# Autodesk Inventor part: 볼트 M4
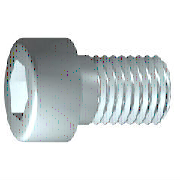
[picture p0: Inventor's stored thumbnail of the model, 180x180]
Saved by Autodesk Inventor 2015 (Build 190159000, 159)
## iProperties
IsCustomPart: 1
Created: 2012-02
Part Number: 볼트 M4
Material: 스테인리스강
Description: 6각 소켓 머리 캡 나사
Document SubType Name: Modeling
Standard: ISO 4762
Designer: mduedu
Standard Revision: Fourth edition 2004-03-01
Standards Organization: ISO
Language: ko-KR
Size Designation: M4 x 10
Categories: <MemberInstance><Categories><Category DisplayName="조임쇠" InternalName="e4da775c-781d-43d5-af7c-5136215cf5a6" Mnemonic="FSTN"><Category DisplayName="볼트" InternalN
Density: 7.75 g/cm^3
Appearance: 반광택
Author: mduedu
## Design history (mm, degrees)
sketch "스케치1"
  geometry: L1 (-1, 0)-(10, 0); L2 (10, 0)-(10, 2); L3 (10, 2)-(1.75, 2); L4 (1.75, 2)-(1.32, 2); L5 (1.32, 2)-(0, 2); L6 (0, 2)-(0, 3.5); L7 (0, 3.5)-(-4, 3.5); L8 (-4, 3.5)-(-4, 1.732); L9 (-4, 1.732)-(-2, 1.732); L10 (-2, 1.732)-(-1, 0); L11 (-6.8, 0)-(12.8, 0) reference; L12 (0, -0.7)-(0, 4.2) reference; L13 (1.75, 2)-(0, 2)
  constraints: 22 end point, 6 parallel, 2 collinear, 2 perpendicular, 1 horizontal, 1 point on line
  dimensions: "d1" = 8.25 distance from line of L3.end L2 (= GEL); "d2" = 0.42952 distance of L4.end L3.end (computed from GAL); "d3" = 4 distance between parallel lines of L8 L6 (= KOH); "d4" = 2 distance of L8.end L9.end (= INTI); "d5" = 60 deg angle of L10 L1; "d6" = 4 diameter of L3 L1 (= GD); "d7" = 4 diameter of L5 L1 (= BDM); "d8" = 3.4641 diameter of L9 L1 (= 1.1547 x SW); "d9" = 7 diameter of L7 L1 (= KOD); "d26" = 10 distance between parallel lines of L12 L2 (= NLG)
revolve "본체" sketch "스케치1" stored, may be unused: angle "d10" = 90 deg
sketch "스케치2"
  geometry: L1 (0, -4.9)-(0, 4.9) reference; L2 (-4.9, 0)-(4.9, 0) reference; L3 (1.732, 0)-(0.866, -1.5); L4 (0.866, -1.5)-(-0.866, -1.5); L5 (-0.866, -1.5)-(-1.732, 0); L6 (-1.732, 0)-(-0.866, 1.5); L7 (-0.866, 1.5)-(0.866, 1.5); L8 (0.866, 1.5)-(1.732, 0); 2 further points
  constraints: 12 end point, 1 coincident, 1 horizontal alignment, 1 point on line, 12 other
extrude "슬롯" join sketch "스케치2" stored distance "d11" = 10; taper "d12" = 0 deg
workplane "Work Plane1"
body "Solid1"
fillet "모깎기1" dims "d17" = 0.4 (= RR)
feature "스레드" dims "d13" = 8.25 (= GEL), "d14" = 0
chamfer "모따기1" distance "d15" = 0.42941 (= -0.5 x SPD + 0.5 x GD); stored, may be unused: second distance "d16" = 0.42941 (= GUL), angle "d27" = 45 deg
other parameters: "GD" = 4 [user parameter; used in 2 equation terms], "NLG" = 10 [user parameter; used in 1 equation term], "GEL" = 8.25 [user parameter; used in 2 equation terms], "KOD" = 7 [user parameter; used in 1 equation term], "KOH" = 4 [user parameter; used in 1 equation term], "INTI" = 2 [user parameter; used in 1 equation term], "GAL" = 0.42941 (= 0.61345 x PTC) [user parameter; used in 1 equation term], "GUL" = 0.42941 (= 0.61345 x PTC) [user parameter; used in 1 equation term], "BDM" = 4 (= NND) [user parameter; used in 1 equation term], "SW" = 3 [user parameter; used in 2 equation terms], "RR" = 0.4 [user parameter; used in 1 equation term], "SPD" = 3.14117 (= NND - 1.2269 x PTC) [user parameter; used in 1 equation term], "d19" = 0, "d28" = 0, "d29" = 0, "R" = 0.1 [user parameter], "TOA" = 30 deg [user parameter], "GD1" = 3.14117 (= THREADDIA - 1.2269 x PTC) [user parameter], "THREADDIA" = 4 [user parameter; used in 1 equation term], "FAWI" = 45 deg [user parameter], "TPU" = 14.28571 (computed from PTC) [user parameter], "PTC" = 0.7 [user parameter; used in 5 equation terms], "NND" = 4 [user parameter; used in 2 equation terms], "E0" = 3.465 (= 1.155 x SW) [user parameter]
